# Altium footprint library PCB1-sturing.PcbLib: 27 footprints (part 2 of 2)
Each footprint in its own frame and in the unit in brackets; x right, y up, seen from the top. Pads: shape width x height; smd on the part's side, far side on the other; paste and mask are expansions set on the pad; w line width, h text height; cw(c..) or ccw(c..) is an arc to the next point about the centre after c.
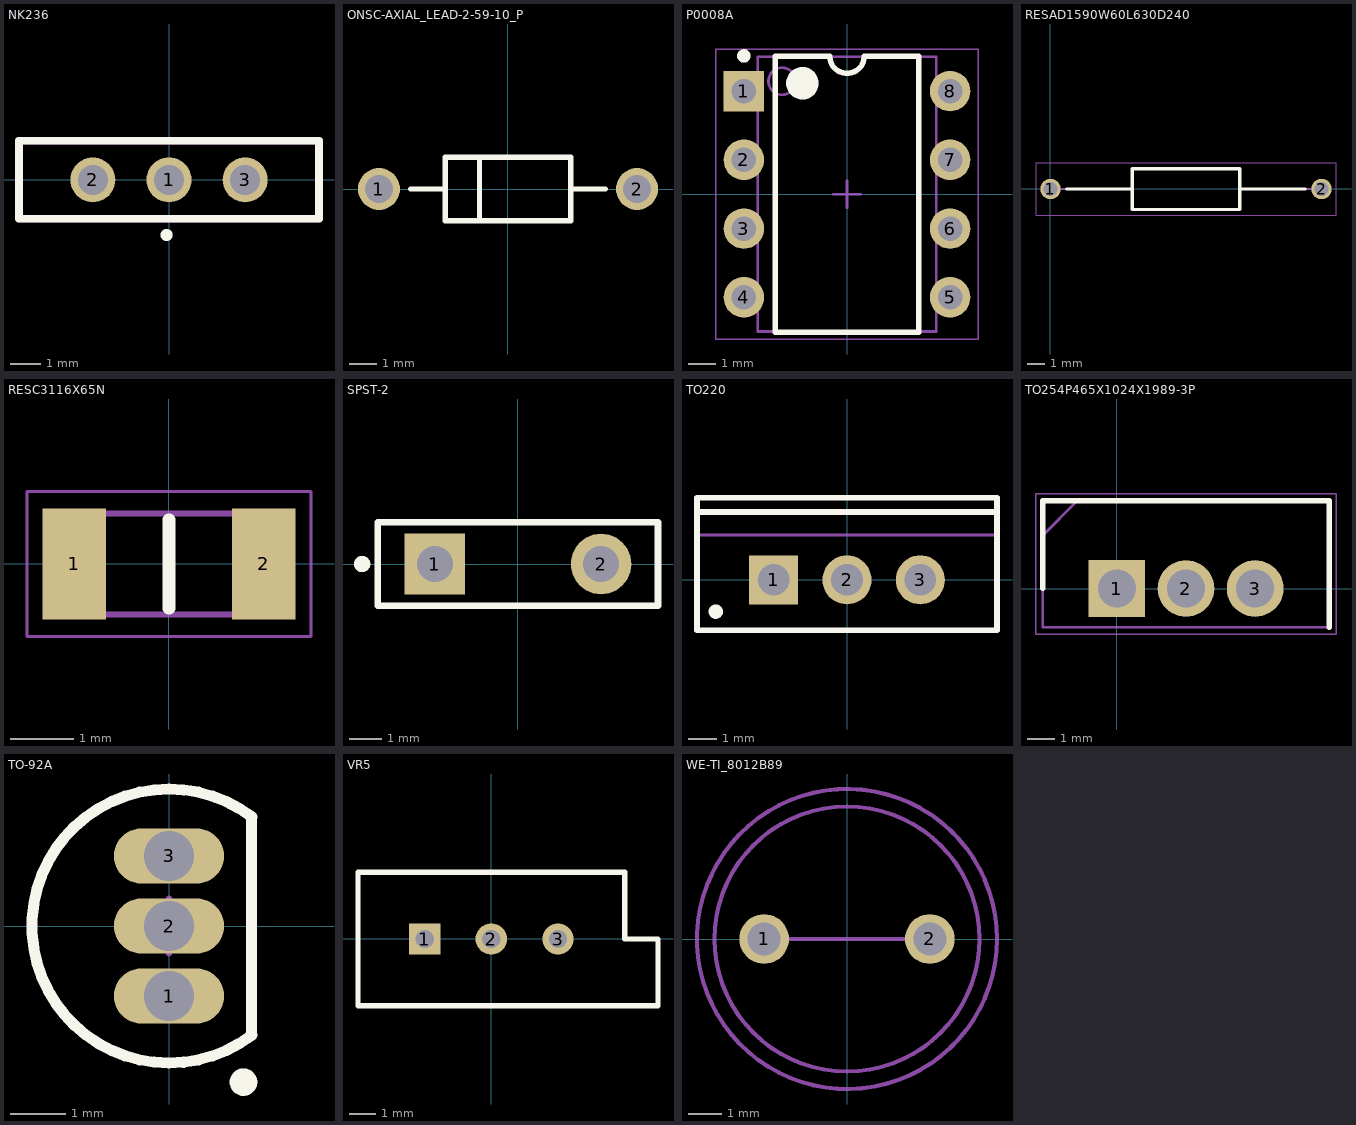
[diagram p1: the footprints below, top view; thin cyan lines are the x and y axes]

## NK236 [mm]
pads (3):
  round 1.5 hole 1: 1(0,0) 2(-2.54,0) 3(2.54,0)
Top Overlay:
  circle w0.254: c-0.081,-1.838 r0.073
  lines w0.254: -5,-1.3 5,-1.3 5,1.3 -5,1.3 -5,-1.3
Mechanical 13:
  lines w0.254: -5,-1.3 -5,1.3 5,1.3 5,-1.3 -5,-1.3
3D body "NK236.stp": height 1.3, standoff -1.3, extent -5,-5.4 5,6.1

## ONSC-AXIAL_LEAD-2-59-10_P [mm] "AXIAL, 2-Leads, Diameter 2.35mm"
height 2.35
pads (2):
  round 1.55 hole 1.05: 1(-4.77,0) 2(4.77,0)
Top Overlay:
  lines w0.2: -3.595,0 -2.325,0 ; -1.055,-1.175 -1.055,1.175 ; 2.325,0 3.595,0 ; -2.325,-1.175 -2.325,1.175 2.325,1.175 2.325,-1.175 -2.325,-1.175

## P0008A [mm] "DIP, 8-Leads, Body 10.15x6.6mm, Pitch 2.54mm"
height 5.08
pads (8):
  rect 1.5x1.5 hole 0.9: 1(-3.81,3.81)
  round 1.5 hole 0.9: 2(-3.81,1.27) 3(-3.81,-1.27) 4(-3.81,-3.81) 5(3.81,-3.81) 6(3.81,-1.27) 7(3.81,1.27) 8(3.81,3.81)
Top Overlay:
  circle w0.25: c-3.81,5.11 r0.125
  circle w0.6: c-1.65,4.1 r0.3
  lines w0.2: -2.65,-5.1 -2.65,5.1 -0.635,5.1 ccw(c0,5.1) 0.635,5.1 2.65,5.1 2.65,-5.1 -2.65,-5.1
Mechanical 13:
  circle w0.1: c-2.4,4.175 r0.5
  lines w0.1: -3.3,-5.075 -3.3,5.075 3.3,5.075 3.3,-5.075 -3.3,-5.075
Mechanical 15:
  lines w0.05: -4.85,-5.35 -4.85,5.35 4.85,5.35 4.85,-5.35 -4.85,-5.35
  lines w0.1: -0.5,0 0.5,0 ; 0,-0.5 0,0.5
3D body: height 2.66, standoff 0, extent -3.945,3.31 -3.675,4.31
3D body: height 2.93, standoff 2.66, extent -3.945,3.31 -3.3,4.31
3D body: height 0, standoff -1.6, extent -3.945,3.45 -3.675,4.17
3D body: height 2.66, standoff 0, extent -3.945,0.77 -3.675,1.77
3D body: height 2.93, standoff 2.66, extent -3.945,0.77 -3.3,1.77
3D body: height 0, standoff -1.6, extent -3.945,0.91 -3.675,1.63
3D body: height 2.66, standoff 0, extent -3.945,-1.77 -3.675,-0.77
3D body: height 2.93, standoff 2.66, extent -3.945,-1.77 -3.3,-0.77
3D body: height 0, standoff -1.6, extent -3.945,-1.63 -3.675,-0.91
3D body: height 2.66, standoff 0, extent -3.945,-4.31 -3.675,-3.31
3D body: height 2.93, standoff 2.66, extent -3.945,-4.31 -3.3,-3.31
3D body: height 0, standoff -1.6, extent -3.945,-4.17 -3.675,-3.45
3D body: height 2.66, standoff 0, extent 3.675,-4.31 3.945,-3.31
3D body: height 2.93, standoff 2.66, extent 3.3,-4.31 3.945,-3.31
3D body: height 0, standoff -1.6, extent 3.675,-4.17 3.945,-3.45
3D body: height 2.66, standoff 0, extent 3.675,-1.77 3.945,-0.77
3D body: height 2.93, standoff 2.66, extent 3.3,-1.77 3.945,-0.77
3D body: height 0, standoff -1.6, extent 3.675,-1.63 3.945,-0.91
3D body: height 2.66, standoff 0, extent 3.675,0.77 3.945,1.77
3D body: height 2.93, standoff 2.66, extent 3.3,0.77 3.945,1.77
3D body: height 0, standoff -1.6, extent 3.675,0.91 3.945,1.63
3D body: height 2.66, standoff 0, extent 3.675,3.31 3.945,4.31
3D body: height 2.93, standoff 2.66, extent 3.3,3.31 3.945,4.31
3D body: height 0, standoff -1.6, extent 3.675,3.45 3.945,4.17
3D body: height 5.08, standoff 0.51, extent -3.3,-5.075 3.3,5.075

## RESAD1590W60L630D240 [mm]
pads (2):
  round 1.2 hole 0.8: 1(0,0) 2(15.9,0)
Top Overlay:
  lines w0.2: 0.95,0 4.8,0 ; 11.1,0 14.95,0 ; 4.8,-1.2 11.1,-1.2 11.1,1.2 4.8,1.2 4.8,-1.2
Mechanical 13:
  lines w0.1: 0,0 4.8,0 ; 11.1,0 15.9,0 ; 4.8,-1.2 11.1,-1.2 11.1,1.2 4.8,1.2 4.8,-1.2
Mechanical 15:
  lines w0.05: -0.85,-1.55 16.75,-1.55 16.75,1.55 -0.85,1.55 -0.85,-1.55
3D body "MF0207FTE52-10K.stp": height 0, standoff 0, extent 0,0 0,0

## RESC3116X65N [mm]
pads (2):
  rect 1x1.75 smd: 1(-1.5,0) 2(1.5,0)
Top Overlay:
  lines w0.2: 0,-0.7 0,0.7
Mechanical 13:
  lines w0.1: -1.55,-0.8 -1.55,0.8 1.55,0.8 1.55,-0.8 -1.55,-0.8
Mechanical 15:
  lines w0.05: -2.25,-1.15 -2.25,1.15 2.25,1.15 2.25,-1.15 -2.25,-1.15
3D body "RC1206JR-07_10KL.stp": height 0.65, standoff 0, extent -1.55,-0.8 1.55,0.8

## SPST-2 [mm] "Switch; 2 Leads"
pads (2):
  rect 1.85x1.85 hole 1.1: 1(-2.54,0)
  round 1.85 hole 1.1: 2(2.54,0)
Top Overlay:
  circle w0.25: c-4.761,-0.001 r0.125
  lines w0.2: -4.28,-1.27 4.28,-1.27 4.28,1.27 -4.28,1.27 -4.28,-1.27

## TO220 [mm] "TO, Thru-Hole, Vertical, Heatsink Mounted; 3 In-Line Leads; Pitch 2.54 mm"
height 19.7
pads (3):
  rect 1.7x1.7 hole 1.1: 1(-2.54,0)
  round 1.7 hole 1.1: 2(0,0) 3(2.54,0)
Top Overlay:
  circle w0.25: c-4.55,-1.1 r0.125
  lines w0.2: -5.2,2.35 5.2,2.35 ; -5.2,-1.75 -5.2,2.85 5.2,2.85 5.2,-1.75 -5.2,-1.75
Mechanical 13:
  lines w0.1: -5.2,1.55 5.2,1.55 ; -5.2,-1.75 5.2,-1.75 5.2,2.85 -5.2,2.85 -5.2,-1.75
Mechanical 15:
  lines w0.1: -0.5,0 0.5,0 ; 0,-0.5 0,0.5
3D body: height 19.7, standoff 13.05, extent -5.199,1.551 5.199,2.849
3D body: height 13.05, standoff 3.5, extent -5.25,-1.8 5.25,2.9

## TO254P465X1024X1989-3P [mm]
pads (3):
  rect 2.085x2.085 hole 1.39: 1(0,0)
  round 2.085 hole 1.39: 2(2.54,0) 3(5.08,0)
Top Overlay:
  lines w0.2: -2.72,0 -2.72,3.225 7.8,3.225 7.8,-1.425
Mechanical 13:
  lines w0.1: -2.72,1.955 -1.45,3.225 ; -2.72,-1.425 -2.72,3.225 7.8,3.225 7.8,-1.425 -2.72,-1.425
Mechanical 15:
  lines w0.05: -2.97,-1.675 -2.97,3.475 8.05,3.475 8.05,-1.675 -2.97,-1.675
3D body "IRF730.stp": height 18.77, standoff -17.37, extent -2.58,-1.425 7.66,3.225

## TO-92A [mm] "TO, Flat Index; 3 In-Line, Axial Leads; Body Dia. 4.5mm; Leads 0.51 x 0.48 mm (max)"
height 6.86
pads (3):
  oval 2x1 hole 0.9: 1(0,-1.27) 2(0,0) 3(0,1.27)
Top Overlay:
  circle w0.25: c1.35,-2.83 r0.125
  lines w0.2: 1.5,-1.98 cw(c0,0) 1.5,1.98 1.5,-1.98
Mechanical 13:
  lines w0.1: 1.5,-1.98 cw(c0,0) 1.5,1.98 1.5,-1.98
Mechanical 15:
  lines w0.1: -0.5,0 0.5,0 ; 0,-0.5 0,0.5
3D body: height 6.86, standoff 2.2, extent -2.485,-2.495 1.501,2.495

## VR5 [mm] "Thru-Hole; 3 Leads"
pads (3):
  rect 1.2x1.2 hole 0.7: 1(-2.54,0)
  round 1.2 hole 0.7: 2(0,0) 3(2.54,0)
Top Overlay:
  lines w0.2: -5.08,-2.54 6.35,-2.54 6.35,0 5.08,0 5.08,2.54 -5.08,2.54 -5.08,-2.54

## WE-TI_8012B89 [mm]
pads (2):
  round 1.5 hole 1: 1(-2.5,0) 2(2.5,0)
Mechanical 13:
  circle w0.127: c0,0 r4
  lines w0.127: -2.5,0 2.5,0
Mechanical 15:
  circle w0.127: c0,0 r4.528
